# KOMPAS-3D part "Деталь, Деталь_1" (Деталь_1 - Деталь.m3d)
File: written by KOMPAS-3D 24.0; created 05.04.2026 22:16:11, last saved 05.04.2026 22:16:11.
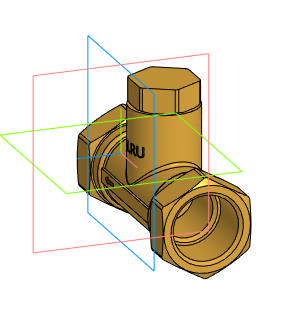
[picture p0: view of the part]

Document properties: Автор: tyuri; Полное имя файла: D:\Аутсорс\Клапан балансировочный автоматический DN.ru VBA0000E-T Ду15 Ру16\DN15\Деталь_1 - Деталь.m3d

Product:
- Body: Твердое тело1  | qty 1
- Part/product: Деталь  | designation Деталь_1
    additional columns: Типовые

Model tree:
1. Твердое тело1  (labels: Твердое тело1)

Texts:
  Деталь_1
